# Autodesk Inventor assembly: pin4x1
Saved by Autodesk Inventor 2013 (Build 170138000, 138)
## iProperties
Created: 2021-02
Part Number: pin4x1
Document SubType Name: Assembly
Designer: Fede
Author: Fede
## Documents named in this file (3)
- C:\0000 FEDE\16GB\0000 INTERIOR\DE_TMP_BAS\BAS_DTON - demora conexion al energizar\pcb\BOR\turn on\Imported Components\BAS_DTON\pin4x1.iam
- C:\0000 FEDE\16GB\0000 INTERIOR\DE_TMP_BAS\BAS_DTON - demora conexion al energizar\pcb\BOR\turn on\Imported Components\BAS_DTON\cgrid_1x1_parte2.iam
- C:\0000 FEDE\16GB\0000 INTERIOR\DE_TMP_BAS\BAS_DTON - demora conexion al energizar\pcb\BOR\turn on\Imported Components\BAS_DTON\pin.ipt
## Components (8 placed, 2 different names)
1. cgrid_1x1_parte2:1 [sub-assembly]
2. pin:1
3. cgrid_1x1_parte2:2 [sub-assembly]
4. pin:2
5. cgrid_1x1_parte2:3 [sub-assembly]
6. pin:3
7. cgrid_1x1_parte2:4 [sub-assembly]
8. pin:4
